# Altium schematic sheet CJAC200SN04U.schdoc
size 127 x 101 mm
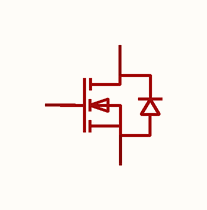
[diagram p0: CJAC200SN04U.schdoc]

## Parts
U?  cjac200sn04u  [PDFNWB-8L_L6.0-W5.0-P1.27-BL-EP]  (value not drawn)

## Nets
NetU?_1: U?.1(S) U?.2(S) U?.3(S)
NetU?_5: U?.5(D) U?.6(D) U?.7(D) U?.8(D)

Not connected (* = marked no-connect by the designer): U? 4(G)

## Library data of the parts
U? = cjac200sn04u: 类型:1个N沟道;漏源电压(Vdss):40V;连续漏极电流(Id):200A;导通电阻(RDS(on)@Vgs,Id):1.05mΩ@4.5V,30A;功率:104W;阈值电压(Vgs(th)@Id):1.3V@250uA;; Manufacturer: CJ(江苏长电/长晶); AddInBom: yes; ModelId: e3e175b3db6c4f90a9ad9ca232f97958; ModelName: POWERVDFN-8_L6.0-W5.0-H1.0-P1.27; ModelTransform: 207.878,240.157,0,0,0,0,0,0,0; Drain Source Voltage (Vdss): 40V; Continuous Drain Current (Id): 200A; Power Dissipation (Pd): 104W; Total Gate Charge (Qg@Vgs): 124nC@10V; Input Capacitance (Ciss@Vds): 9.107nF@20V; Reverse Transfer Capacitance (Crss@Vds): 89pF@20V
